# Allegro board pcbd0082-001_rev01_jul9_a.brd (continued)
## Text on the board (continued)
User.38: MARKINGS: | 11.1 UL MARKING, MANUFACTURER'S IDENTIFICATION, AND DATE CODE SHALL BE RENDERED IN ETCH ON | TESTING: | 12.1 BARE BOARD ELECTRICAL TEST TO BE PERFORMED WITH SUPPLIED IPC-D-356 (CURRENT REVISION) | THIEVING: | 13.1 THIEVING REQUIRES APPROVAL BY NETRONOME.THIEVING MAY BE ADDED TO ACHIEVE PLATING | 14 VENDOR SHALL REMOVE ALL NON FUNCTIONAL PADS FROM THE INTERNAL SIGNAL LAYERS. | 17.1 TRACE GEOMETRIES USED IN DATABASE ARE REFERENCED BELOW. NOTIFY NETRONOME SYSTEMS IF FINISHED | 17.2 REFER TO TABLE BELOW FOR CONTROLLED IMPEDANCE REQUIREMENTS. UNLESS OTHERWISE STATED, | 16.1 IMPEDANCE REPORT, ELECTRICAL TEST CERTIFICATION, AND CROSS SECTION REPORTS | 15 IF APPLICABLE, VENDOR MAY ADD TEARDROPS TO SIGNAL LAYERS AT PAD/TRACE JUNCTION. | SILKSCREEN: | 10.1 SILKSCREEN SHALL BE WHITE, PERMANENT, AND NON-CONDUCTIVE EPOXY INK PER SUPPLIED | 17.3 IMPEDANCE BELOW MIGHT NOT EXIST ON ANY GIVEN LAYER, SEE NOTE 18 FOR DETAILED INFORMATION. | 1 FABRICATE PCB IN ACCORDANCE WITH IPC-6012 (CURRENT REVISION), CLASS 2 USING SUPPLIED | 2 PCB MUST MEET OR EXCEED ACCEPTABLIITY REQUIREMENTS AS DEFINED IN IPC-A-600 (CURRENT | 3 FABRICATION DRAWING TAKES PRECEDENCE OVER THE SPECIFICATIONS. | MATERIALS: | 4.1 LAMINATE AND PREPREG TO BE IN ACCORDANCE WITH IPC-4101(CURRENT REVISION). | 4.4.2 MATERIAL THICKNESS IS OVER EDGE FINGERS IF APPLICABLE | 4.4.3 STACKUP INFORMATION IS FOR REFERENCE ONLY. FINAL STACKUP INFORMATION MUST | 4.2 COPPER FOIL TO BE IN ACCORDANCE WITH IPC-4562 (CURRENT REVISION). | 4.3 COPPER WEIGHT: | 4.3.1 OUTER LAYERS - 1oz MINIMUM. OUTER LAYER WEIGHT IS TO BE CONSIDERED "FINISHED". | 4.4.1 REFER TO STACK-UP DETAIL FOR LAYER SEQUENCE AND MATERIAL THICKNESS. | DRILL: | 5.1 ALL DIMENSIONS AND HOLE SIZES ARE FINISHED SIZES. PCB SHALL BE ROUTED TO FINISHED | 5.2 ALL HOLES SHALL BE NC DRILLED AND PLATED PER DRILL TABLE. SIZES ARE FINISHED SIZES. | 5.3 ALL HOLES SHALL BE LOCATED WITHIN +/-0.008" DIAMETER OF TRUE POSITION. LAYER TO | ANNULAR RING: | 6.1 EXTERNAL SUPPORTED HOLES - 0.001" MINIMUM. | 6.2 INTERNAL SUPPORTED HOLES - TANGENCY MINIMUM. | 6.3 UNSUPPORTED HOLES        - TANGENCY MINIMUM. | CONDUCTORS: | 7.1 CONDUCTORS WILL NOT EXCEED A REDUCTION IN WIDTH OR SPACING BY MORE THAN 20% OR 0.002", | SURFACE FINISH: | 8.1 PCB SURFACE FINISH SHALL BE IMMERSION SILVER. HARD GOLD ON FINGERS | SOLDERMASK: | 9.1 APPLY LIQUID PHOTO IMAGEABLE SOLDERMASK(BLUE) PER IPC-SM-840 (CURRENT | 4.3.2 INNER LAYERS - PLANE- 1.0oz.. SIGNAL- 0.5oz. | NOTES: | 9.2 IF NECESSARY, INSUFFICIENT SOLDEMASK DAMS LESS THAN THAN 0.004 CAN BE REMOVED. | 4.4 STACK-UP: | 9.3 THE SOLDERMASK OPENINGS FOR U1 ARE PROVIDED, NO MODIFICATION ALLOWED. | REVISION) CLASS T TO BOTH SIDES OF THE PCB OVER BARE COPPER PER SUPPLIED FILES. | REPORTS: | THE SECONDARY SIDE OF THE BOARD WHERE INDICATED OR WHERE ROOM PERMITS. SECONDARY SIDE | SILKSCREEN MAY BE USED AS AN ALTERNATIVE. | NETLIST. TEST CERTIFICATION TO ACCOMPANY BOARDS WHEN SHIPPED. | BALANCE PROVIDING A MINIMUM 0.150"CLEARANCE FROM COPPER FEATURES, AND 0.250" CLEARANCE | FROM NON-PLATED HOLES UNLESS STATED OTHERWISE. | IMPEDANCE CALCULATIONS: | TRACE IS LARGER THAN THE TRACE SPECIFIED, OR WILL FINISH LESS THAN 0.005" WIDE AT THE BASE | ON INNER SIGNAL LAYERS, OR 0.006" ON THE OUTER LAYERS. | IMPEDANCE TOLERANCE IS +/- 10%. | TO ACCOMPANY SHIPMEMT | FILES. IT SHOULD BE SHARP AND CLEAR, FREE OF SMUDGES.SILKSCREEN MUST BE CLIPPED SO AS NOTE | TO CONTACT ANY SOLDERABLE COMPONENT PAD OR TESTPOINT VIA, AND NOT FLOW INTO HOLE WALLS. | FR4 MATERIAL TO BE HIGH Tg AND MEET OR EXCEEDS UL94V-0.. | DATA FILES. REFER TO INCLUDED README.TXT FILE FOR A LIST OF PROVIDED DATA FILES. | REVISION) CLASS 2. | SIZE +/-0.010" UNLESS OTHERWISE NOTED OR DIMENSIONED. | LAYER REGISTRATION SHALL BE WITHIN 0.005". | WHICHEVER MINIMUM VALUE IS LESS. | BE APPROVED BY NETRONOME SYSTEMS. | TYPE | DIFF | SE | LAYER | 7 | 10 | 3 | 4 | 1 | 8 | 0.00434 | 0.00546 | 0.0058 | 0.00475 | 0.00391 | 0.00378 | 0.00743 | WIDTH | LINE | 0.010 | 0.00834 | 0.00925 | 0.01025 | CENTER | TO | NA | TOP | 6 | 9 | 2 | REF PLANE | BOTTOM | 5 | 40 OHMS | 50 OHMS | 85 OHMS | 100 OHMS | IMPEDANCE
User.39: PREPREG .0038 | CORE .0040 | PREPREG .0091 | PREPREG .0076 | LAYER 2 PLN | LAYER 3 SIG | LAYER 4 SIG | LAYER 5 PLN | LAYER 6 PLN | LAYER 7 SIG | LAYER 8 SIG | LAYER 9 PLN | TOP 1 | BOTTOM 10 | * COPPER THICKNESS IS MINIMUM FINISHED | THICKNESS- BASE THICKNESS PLUS PLATING | STACK-UP IS FOR REFERENCE ONLY | FINISHED BOARD THICKNESS | 0.062 +/- .006 | 1.5oz | 1.0oz | 0.5oz | *
User.40: 19. VIA FILL: | 18 SEE PCBD0082_STACKUP.PDF DOCUMENT FOR COMPLETE STACKUP. | (SAN EI-PHP-900 OR EQUIVALENT MATERIAL), OVERPLATED WITH COPPER, AND | PLANARIZED TO THE SURFACE. MAXIMUM DIMPLE NOT TO EXCEED IPC-6012 (LATEST REVISION). | VIAS SHOWN ON VIAFILL.ART (0.0081 AND 0.0101 VIAS) SHALL BE FILLED WITH NON-CONDUCTIVE MATERIAL | IT IS ACCEPTABLE TO FILL ALL VIAS (.008 THRU .0101) AT VENDOR DISCRETION AND | NETRONOME APPROVAL
User.44: R331 | C31 | R4 | A | DS1 | R119 | L11 | C | C131 | C133 | C141 | L19 | C32 | R395 | R34 | C282 | R372 | L20 | C284 | R63 | R68 | C68 | L12 | L1 | R381 | C278 | C142 | U20 | C279 | U12 | C12 | R382 | C58 | C1 | R87 | R85 | R88 | R86 | R3 | C125 | R323 | C11 | R1 | 14 | R268 | R139 | R263 | R262 | R138 | R15 | L7 | R118 | C35 | C34 | C10 | R324 | R315 | 1 | C124 | R180 | R181 | R110 | R314 | R325 | C281 | P | C4 | C24 | C83 | R133 | R132 | R134 | R135 | L15 | 32 | C143 | R279 | R101 | R122 | R402 | R117 | R76 | C46 | R278 | D5 | R205 | R400 | R202 | R281 | R204 | R178 | U4 | R405 | C249 | R282 | R201 | R398 | C119 | R168 | L13 | R50 | R48 | C62 | C63 | C64 | C65 | R58 | R167 | C122 | R148 | R404 | R147 | R43 | C118 | C120 | C181 | R369 | L21 | R403 | R200 | R44 | R166 | R379 | C183 | R59 | R89 | C126 | R171 | C217 | R340 | R338 | C266 | C2 | AM | C265 | C214 | C212 | C219 | R364 | C110 | R8 | R7 | C285 | C184 | L9 | C66 | R388 | R335 | C213 | C51 | C71 | R289 | R385 | R277 | R276 | C108 | U3 | C220 | R127 | C211 | C216 | U21 | R337 | Q1 | C130 | R108 | C129 | R387 | R386 | U9 | R272 | R310 | R188 | R170 | C170 | R144 | R186 | R283 | C196 | C29 | R187 | C186 | R145 | C78 | C39 | C38 | C91 | C41 | C42 | C101 | C102 | C43 | C94 | C93 | C176 | C269 | C272 | C271 | C268 | C275 | R285 | R286 | R321 | R320 | C27 | C26 | C25 | C86 | U13 | 2 | 3 | 4 | 5 | 6 | 7 | 8 | R103 | R100 | R131 | C205 | R130 | C128 | R98 | C165 | R104 | C136 | L10 | C137 | C22 | C140 | C135 | C20 | R367 | R368 | C134 | C179 | R389 | R390 | C19 | R396 | R392 | C202 | R350 | R73 | C132 | C23 | R391 | C201 | R371 | R393 | R62 | C21 | C67 | C87 | R67 | R126 | R71 | R384 | C154 | R116 | R21 | R70 | R72 | C153 | R75 | C47 | R61 | R312 | C15 | R22 | C144 | R64 | R383 | C156 | R66 | R65 | C16 | R23 | C155 | R69 | C82 | R60 | C157 | R308 | R84 | C81 | C158 | R351 | R83 | R120 | C159 | C18 | R92 | R326 | C48 | C160 | C17 | R93 | C146 | R328 | C52 | R96 | L3 | C5 | C3 | R313 | C13 | C14 | L2 | C7 | C145 | C49 | R94 | C180 | R182 | C147 | C50 | R90 | C148 | R287 | U14 | R91 | R269 | C149 | R77 | R13 | R14 | C150 | R78 | R327 | R80 | C151 | C33 | R329 | C280 | R79 | C152 | R111 | C204 | R401 | C203 | R317 | R74 | C61 | C248 | R267 | R169 | C60 | R203 | R408 | R316 | C59 | C57 | L14 | C182 | R102 | R81 | C121 | R121 | R173 | R177 | R397 | R159 | R82 | R264 | R49 | R174 | C36 | C84 | R55 | R175 | R95 | R52 | R172 | R53 | R54 | R176 | R57 | R149 | R97 | R56 | R47 | R411 | R179 | R410 | R27 | R31 | C123 | R370 | R2 | R26 | R29 | R380 | R24 | R25 | R20 | C127 | R30 | C85 | R32 | R28 | R99 | R399 | R18 | R112 | R113 | R339 | R152 | C105 | R362 | R288 | R363 | R361 | C264 | C206 | C111 | C139 | C263 | R354 | R106 | R225 | C109 | C138 | R352 | C283 | R189 | R229 | R231 | R318 | R226 | R224 | R353 | R216 | R227 | R107 | R376 | C215 | R109 | R223 | R222 | R375 | R394 | C218 | R218 | R206 | R377 | R207 | R210 | R208 | R378 | R217 | R212 | R215 | R374 | R373 | R220 | R214 | R219 | R105 | R209 | R211 | R213 | C192 | C191 | C76 | R146 | C193 | R124 | C190 | C194 | C195 | R284 | C116 | C187 | C80 | C37 | C169 | C177 | C168 | C89 | C166 | C8 | C199 | C90 | C198 | C161 | C30 | C163 | C28 | C44 | C162 | C173 | C77 | C9 | C197 | C103 | C174 | C171 | C178 | C175 | C40 | C200 | C172 | C92 | R319 | R322 | C167 | C79 | C277 | C276 | C273 | R409 | C270 | R199 | R16 | R365 | C274 | R46 | R19 | R406 | R41 | R45 | C74 | R407 | R42 | 153 | 154 | 155 | 156 | 157 | 158 | 159 | 160 | ASSEMBLY DRAWING SECONDARY SIDE | ASSEMBLY DRAWING PRIMARY SIDE | U17 | U18 | U19 | U6 | U15 | U8 | U10 | U2 | U5 | L18 | U1 | U7 | L17 | J5 | J4 | C242 | C243
User.45: FIGURE | SIZE | 5.0 | DRILL CHART: TOP to 02_GND | ALL UNITS ARE IN MILS | TOLERANCE | +0.0/-5.0 | PLATED | QTY | 34 | 8.1 | 10.0 | 10.1 | 10.5 | 20.0 | 30.0 | 50.0 | 125.0 | 126.0 | 157.48 | DRILL CHART: TOP to BOTTOM | +0.0/-8.1 | +0.0/-10.0 | +0.0/-10.1 | +0.0/-10.5 | +3.0/-3.0 | +2.0/-2.0 | NON-PLATED | 1078 | 357 | 429 | 81 | 12 | 20 | 2
